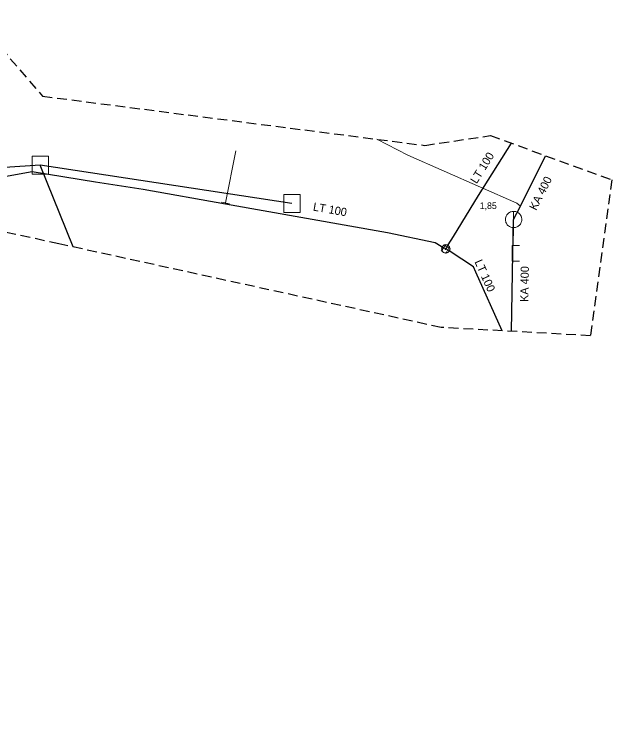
# Model space of a CAD drawing. Extents: x -688693 to -688474, y -974081 to -973994.
# Drawn here: x -688547.3 to -688474.1, y -974081 to -973994.2 of the extents above; entities that cross this region are included whole.
import ezdxf

# ---------------------------------------------------------------- set-up
doc = ezdxf.new("R2010")
doc.units = 0
doc.header["$LTSCALE"] = 0.4
doc.linetypes.add('MEDIUM_DASHED', pattern=[4.5, 3, -1.5])
for name, color, linetype, lineweight in [('1', 7, 'MEDIUM_DASHED', 25), ('11', 7, 'Continuous', 13), ('13', 7, 'Continuous', 13), ('14', 7, 'Continuous', 25), ('17', 7, 'Continuous', 25), ('22', 7, 'Continuous', 13), ('31', 7, 'Continuous', 13), ('34', 7, 'Continuous', 13), ('47', 7, 'Continuous', 13)]:
    doc.layers.add(name, color=color, linetype=linetype, lineweight=lineweight)

msp = doc.modelspace()

# ---------------------------------------------------------------- linework, layer by layer
at = {"layer": '1'}
msp.add_lwpolyline([(-688692.931, -974052.713), (-688674.241, -974042.463), (-688662.987, -974051.708), (-688552.455, -973994.231), (-688543.813, -974004.28), (-688496.988, -974010.309), (-688488.949, -974009.103), (-688474.077, -974014.529), (-688476.69, -974033.621), (-688494.978, -974032.616), (-688541.804, -974022.367), (-688555.67, -974019.352), (-688572.552, -974027.19), (-688578.982, -974032.415), (-688581.193, -974043.669), (-688636.057, -974069.393), (-688655.149, -974067.182), (-688651.532, -974076.829), (-688666.202, -974081.049), (-688669.82, -974071.805), (-688685.294, -974080.647), (-688689.113, -974064.369), (-688682.883, -974060.751)], close=True, dxfattribs=at)
at = {"layer": '11'}
for p, q in [((-688502.844, -974009.555), (-688499.048, -974011.504)), ((-688486.187, -974023.538), (-688486.28, -974023.537))]:
    msp.add_line(p, q, dxfattribs=at)
msp.add_lwpolyline([(-688499.048, -974011.504), (-688485.71, -974017.394), (-688485.472, -974017.595), (-688485.277, -974017.746)], dxfattribs=at)
at = {"layer": '13'}
msp.add_line((-688521.392, -974017.361), (-688520.153, -974010.982), dxfattribs=at)
at = {"layer": '14'}
for p in [(-688513.289, -974017.427), (-688540.045, -974022.752)]:
    msp.add_line(p, (-688544.118, -974012.713), dxfattribs=at)
at = {"layer": '14', "lineweight": 13}
for p, q in [((-688521.409, -974017.455), (-688521.392, -974017.361)), ((-688494.184, -974023.118), (-688494.423, -974022.987))]:
    msp.add_line(p, q, dxfattribs=at)
at = {"layer": '14'}
for points in [[(-688486.109, -974019.386), (-688485.277, -974017.746), (-688482.193, -974011.568)], [(-688544.118, -974012.713), (-688553.402, -974013.335), (-688562.069, -974015.498), (-688588.977, -974027.483)], [(-688486.366, -974033.089), (-688486.187, -974023.538), (-688486.109, -974019.386)]]:
    msp.add_lwpolyline(points, dxfattribs=at)
at = {"layer": '14', "lineweight": 13}
msp.add_lwpolyline([(-688494.688, -974022.862), (-688494.423, -974022.987), (-688494.263, -974022.745)], dxfattribs=at)
at = {"layer": '17'}
for points in [[(-688494.263, -974022.745), (-688494.114, -974022.475), (-688493.486, -974021.473), (-688490.408, -974016.434), (-688486.377, -974010.041)], [(-688551.906, -974014.715), (-688545.087, -974013.515), (-688537.316, -974014.752), (-688531.5, -974015.651), (-688521.409, -974017.455), (-688501.548, -974020.969), (-688495.708, -974022.214), (-688494.963, -974022.656), (-688494.688, -974022.862)], [(-688487.529, -974033.025), (-688490.734, -974025.835), (-688491.039, -974025.184), (-688493.885, -974023.32), (-688494.184, -974023.118)]]:
    msp.add_lwpolyline(points, dxfattribs=at)
at = {"layer": '22'}
msp.add_line((-688486.109, -974021.386), (-688486.108, -974018.386), dxfattribs=at)
for points in [[(-688545.098, -974011.623), (-688543.065, -974011.623), (-688543.065, -974013.816), (-688545.098, -974013.816)], [(-688514.269, -974016.337), (-688512.236, -974016.337), (-688512.236, -974018.53), (-688514.269, -974018.53)], [(-688485.109, -974019.386), (-688485.114, -974019.277), (-688485.132, -974019.169), (-688485.162, -974019.063), (-688485.202, -974018.962), (-688485.254, -974018.865), (-688485.316, -974018.775), (-688485.388, -974018.692), (-688485.468, -974018.618), (-688485.556, -974018.552), (-688485.65, -974018.497), (-688485.75, -974018.452), (-688485.855, -974018.419), (-688485.962, -974018.397), (-688486.071, -974018.387), (-688486.181, -974018.389), (-688486.289, -974018.403), (-688486.396, -974018.428), (-688486.499, -974018.465), (-688486.597, -974018.514), (-688486.689, -974018.572), (-688486.775, -974018.641), (-688486.852, -974018.718), (-688486.921, -974018.804), (-688486.98, -974018.896), (-688487.028, -974018.994), (-688487.065, -974019.097), (-688487.091, -974019.204), (-688487.105, -974019.312), (-688487.108, -974019.422), (-688487.098, -974019.531), (-688487.077, -974019.638), (-688487.043, -974019.742), (-688486.999, -974019.842), (-688486.944, -974019.937), (-688486.878, -974020.025), (-688486.804, -974020.105), (-688486.721, -974020.177), (-688486.631, -974020.239), (-688486.535, -974020.291), (-688486.433, -974020.332), (-688486.328, -974020.362), (-688486.22, -974020.38), (-688486.11, -974020.386), (-688486.001, -974020.38), (-688485.893, -974020.362), (-688485.788, -974020.333), (-688485.686, -974020.292), (-688485.589, -974020.24), (-688485.499, -974020.178), (-688485.416, -974020.107), (-688485.341, -974020.027), (-688485.276, -974019.939), (-688485.22, -974019.845), (-688485.176, -974019.745), (-688485.142, -974019.641), (-688485.12, -974019.533), (-688485.11, -974019.424)]]:
    msp.add_lwpolyline(points, close=True, dxfattribs=at)
at = {"layer": '31'}
msp.add_lwpolyline([(-688485.372, -974022.577), (-688486.273, -974022.571), (-688486.287, -974024.502), (-688485.386, -974024.509)], dxfattribs=at)
at = {"layer": '34'}
for p, q in [((-688521.884, -974017.275), (-688520.899, -974017.447)), ((-688494.388, -974022.461), (-688494.988, -974023.261)), ((-688494.701, -974022.503), (-688493.825, -974022.987)), ((-688493.971, -974022.665), (-688494.397, -974023.57))]:
    msp.add_line(p, q, dxfattribs=at)
at = {"layer": '47'}
for points in [[(-688493.97, -974023.2), (-688493.951, -974023.151), (-688493.936, -974023.101), (-688493.927, -974023.05), (-688493.923, -974022.998), (-688493.924, -974022.945), (-688493.932, -974022.893), (-688493.944, -974022.843), (-688493.962, -974022.793), (-688493.984, -974022.747), (-688494.012, -974022.702), (-688494.044, -974022.66), (-688494.081, -974022.623), (-688494.12, -974022.589), (-688494.163, -974022.559), (-688494.209, -974022.534), (-688494.258, -974022.515), (-688494.308, -974022.5), (-688494.36, -974022.491), (-688494.411, -974022.487), (-688494.464, -974022.488), (-688494.516, -974022.496), (-688494.567, -974022.508), (-688494.616, -974022.526), (-688494.663, -974022.548), (-688494.707, -974022.576), (-688494.749, -974022.608), (-688494.787, -974022.644), (-688494.82, -974022.684), (-688494.85, -974022.727), (-688494.875, -974022.773), (-688494.894, -974022.822), (-688494.909, -974022.872), (-688494.919, -974022.924), (-688494.922, -974022.975), (-688494.921, -974023.028), (-688494.914, -974023.08), (-688494.902, -974023.131), (-688494.884, -974023.18), (-688494.861, -974023.227), (-688494.833, -974023.271), (-688494.801, -974023.313), (-688494.766, -974023.351), (-688494.725, -974023.384), (-688494.682, -974023.414), (-688494.636, -974023.439), (-688494.587, -974023.458), (-688494.537, -974023.473), (-688494.486, -974023.483), (-688494.434, -974023.486), (-688494.381, -974023.485), (-688494.329, -974023.478), (-688494.279, -974023.465), (-688494.23, -974023.448), (-688494.183, -974023.425), (-688494.138, -974023.397), (-688494.096, -974023.365), (-688494.059, -974023.329), (-688494.025, -974023.289), (-688493.995, -974023.246)], [(-688494.348, -974023.021), (-688494.344, -974023.013), (-688494.343, -974023.005), (-688494.341, -974022.997), (-688494.341, -974022.989), (-688494.341, -974022.98), (-688494.342, -974022.971), (-688494.344, -974022.963), (-688494.347, -974022.955), (-688494.351, -974022.947), (-688494.355, -974022.94), (-688494.361, -974022.933), (-688494.367, -974022.927), (-688494.373, -974022.921), (-688494.379, -974022.916), (-688494.388, -974022.912), (-688494.396, -974022.908), (-688494.404, -974022.907), (-688494.412, -974022.905), (-688494.42, -974022.905), (-688494.429, -974022.905), (-688494.438, -974022.906), (-688494.446, -974022.908), (-688494.454, -974022.911), (-688494.463, -974022.915), (-688494.469, -974022.919), (-688494.476, -974022.925), (-688494.482, -974022.931), (-688494.488, -974022.937), (-688494.493, -974022.943), (-688494.497, -974022.952), (-688494.501, -974022.96), (-688494.502, -974022.968), (-688494.504, -974022.976), (-688494.504, -974022.984), (-688494.504, -974022.993), (-688494.504, -974023.001), (-688494.501, -974023.01), (-688494.498, -974023.018), (-688494.494, -974023.027), (-688494.49, -974023.033), (-688494.484, -974023.04), (-688494.478, -974023.046), (-688494.472, -974023.052), (-688494.466, -974023.057), (-688494.457, -974023.061), (-688494.449, -974023.065), (-688494.441, -974023.066), (-688494.433, -974023.068), (-688494.425, -974023.068), (-688494.416, -974023.068), (-688494.408, -974023.068), (-688494.399, -974023.065), (-688494.391, -974023.062), (-688494.383, -974023.058), (-688494.376, -974023.054), (-688494.369, -974023.048), (-688494.363, -974023.042), (-688494.357, -974023.036), (-688494.352, -974023.03)]]:
    msp.add_lwpolyline(points, close=True, dxfattribs=at)

# ---------------------------------------------------------------- texts
at = {"layer": '1'}
for s, rotation, p in [('LT 100', 58, (-688490.642, -974015.082)), ('KA 400', 63, (-688483.358, -974018.348)), ('LT 100', 350, (-688510.733, -974018.283)), ('LT 100', 294, (-688490.919, -974024.565)), ('KA 400', 89, (-688484.313, -974029.495))]:
    msp.add_text(s, height=1, rotation=rotation, dxfattribs=at).set_placement(p)
msp.add_text('1,85', height=0.8, dxfattribs=at).set_placement((-688490.255, -974018.094))

doc.saveas('drawing.dxf')
